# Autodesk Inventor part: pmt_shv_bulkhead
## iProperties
Shininess: 64.0
Length Units: 11272
Angle Units: 11279
Time Units: 11290
Mass Units: 11286
Length Display Precision: 3
Angle Display Precision: 2
Compacted: True
Part Number: pmt_shv_bulkhead
Document SubType Name: Modeling
Created: 2004-05
Designer: John Blackburn
Manufacturer: Standard
Standards Organization: Custom
Density: 0.0
Volumn: 0.0
Area: 0.0
PropertySet Name: Model Information
Control State: 0
Master: False
Checked Out: False
Author: John Blackburn
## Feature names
1. Extrusion1
2. Extrusion2
3. Extrusion3
4. Chamfer1
5. Extrusion4
6. Fillet1
7. Revolution2
